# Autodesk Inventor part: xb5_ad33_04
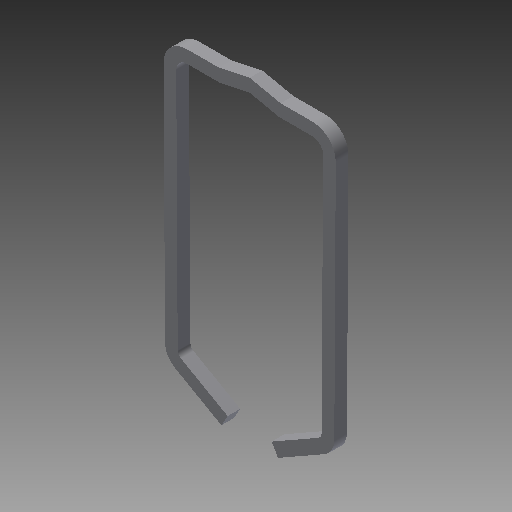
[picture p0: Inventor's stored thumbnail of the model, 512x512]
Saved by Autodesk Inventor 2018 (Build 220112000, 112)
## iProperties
Company: TraceParts S.A.
Created: 2018-05
Part Number: xb5_ad33_04
Checked By: TraceParts S.A.
Material: Generic
Catalog Web Link: www.traceparts.com
Document SubType Name: Modeling
Designer: TraceParts
Density: 1 g/cm^3
Appearance: Default
Author: TraceParts
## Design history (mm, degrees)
feature "xb5_ad33_04.ipt"
body "Solid1"
